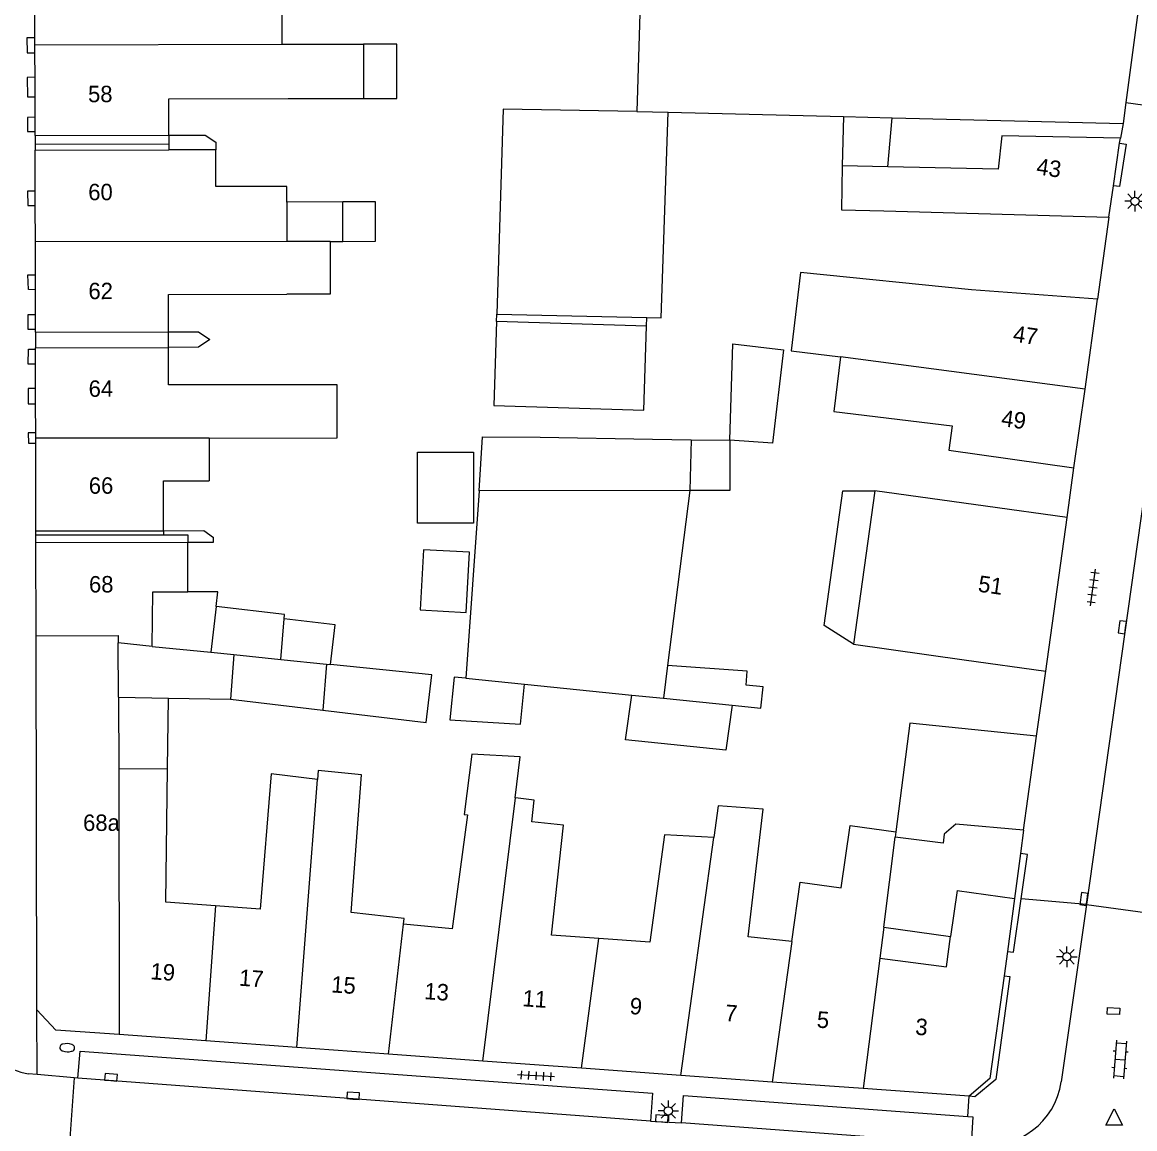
# Model space of a CAD drawing. Extents: x 132998 to 136004, y 396998 to 398512.
# Drawn here: x 133258 to 133325.6, y 397328.9 to 397396.2 of the extents above; entities that cross this region are included whole.
import ezdxf

# ---------------------------------------------------------------- set-up
doc = ezdxf.new("R2010")
doc.units = 0
for name, color, linetype in [('gg-afsc-erfafscheiding', 7, 'Continuous'), ('gg-afsc-muur', 7, 'Continuous'), ('gg-anno-huisnummerreeks BGT', 7, 'Continuous'), ('gg-bbg-bijgebouw', 7, 'Continuous'), ('gg-bbg-gedigitaliseerde bebouwing', 7, 'Continuous'), ('gg-bbg-gedigitaliseerde bebouwing onder overbouw', 7, 'Continuous'), ('gg-bbg-gedigitaliseerde bijgebouw', 7, 'Continuous'), ('gg-bbg-gedigitaliseerde overbouw', 7, 'Continuous'), ('gg-bbg-hoofdgebouw', 7, 'Continuous'), ('gg-bbg-luifel en loopbrug', 7, 'Continuous'), ('gg-bbg-pand overbouw', 7, 'Continuous'), ('gg-bbg-tussenscheiding', 7, 'Continuous'), ('gg-bbg-tussenscheiding niveau 01', 7, 'Continuous'), ('gg-knt-verharding', 7, 'Continuous'), ('gg-knt-verharding nz', 7, 'Continuous'), ('gt-grn-weggrens', 7, 'Continuous'), ('gt-symb-brandkraan', 7, 'Continuous'), ('gt-symb-klinker verharding', 7, 'Continuous'), ('gt-symb-kolk', 7, 'Continuous'), ('gt-symb-kolk center center', 7, 'Continuous'), ('gt-symb-lichtmast', 7, 'Continuous'), ('gt-symb-tegel verharding', 7, 'Continuous'), ('gt-symb-waterafsluiter', 7, 'Continuous')]:
    doc.layers.add(name, color=color, linetype=linetype)

# ---------------------------------------------------------------- blocks, each defined once
blk = doc.blocks.new('gt0-LMAST')
at = {"layer": 'gt-symb-lichtmast'}
for p, q in [((-0.182, 0.173), (-0.447, 0.438)), ((-0.005, 0.246), (-0.005, 0.621)), ((0.172, 0.173), (0.437, 0.438)), ((-0.255, -0.004), (-0.63, -0.004)), ((-0.182, -0.181), (-0.447, -0.446)), ((-0.005, -0.254), (-0.005, -0.629)), ((0.437, -0.446), (0.172, -0.181)), ((0.245, -0.004), (0.62, -0.004))]:
    blk.add_line(p, q, dxfattribs=at)
blk.add_circle((-0.005, -0.004), 0.25, dxfattribs=at)
blk = doc.blocks.new('gt0-TEG1')
at = {"layer": 'gt-symb-tegel verharding'}
for p, q in [((-1.125, 0), (1.125, 0)), ((-0.9, -0.25), (-0.9, 0.25)), ((-0.45, -0.25), (-0.45, 0.25)), ((0, -0.25), (0, 0.25)), ((0.45, -0.25), (0.45, 0.25)), ((0.9, -0.25), (0.9, 0.25))]:
    blk.add_line(p, q, dxfattribs=at)
blk = doc.blocks.new('gt0-KOLK')
at = {"layer": 'gt-symb-kolk'}
blk.add_lwpolyline([(0, 0), (0.375, 0), (0.375, 0.4), (-0.375, 0.4), (-0.375, 0), (0, 0)], dxfattribs=at)
blk = doc.blocks.new('gt0-BR')
at = {"layer": 'gt-symb-brandkraan'}
for centre, radius, start, end in [((-0.244, 0), 0.206, 107.56694, 252.43307), ((0.599, -2.664), 3, 106.89205, 107.56694), ((0, -0.691), 0.938, 73.10799, 106.89205), ((-0.599, -2.664), 3, 72.43309, 73.10799), ((0.244, 0), 0.206, 287.56695, 72.43309), ((0.599, 2.664), 3, 252.43307, 253.10797), ((0, 0.691), 0.938, 253.10797, 286.89206), ((-0.599, 2.664), 3, 286.89206, 287.56695)]:
    blk.add_arc(centre, radius, start, end, dxfattribs=at)
blk = doc.blocks.new('gt0-KOLKCC')
at = {"layer": 'gt-symb-kolk center center'}
blk.add_lwpolyline([(-0.375, 0.2), (0.375, 0.2), (0.375, -0.2), (-0.375, -0.2)], close=True, dxfattribs=at)
blk = doc.blocks.new('gt0-WAFSL')
at = {"layer": 'gt-symb-waterafsluiter'}
for p, q in [((-0.5, -0.333), (0, 0.667)), ((0, 0.667), (0.5, -0.333)), ((0.5, -0.333), (-0.5, -0.333))]:
    blk.add_line(p, q, dxfattribs=at)
blk = doc.blocks.new('gt0-KL1')
at = {"layer": 'gt-symb-klinker verharding'}
for p, q in [((-1.15, 0.3), (1.15, 0.3)), ((-1, -0.3), (-1, 0.3)), ((-0.5, 0.3), (-0.5, 0.45)), ((0, -0.3), (0, 0.3)), ((0.5, 0.3), (0.5, 0.45)), ((1, -0.3), (1, 0.3)), ((-1.15, -0.3), (1.15, -0.3)), ((-0.5, -0.45), (-0.5, -0.3)), ((0.5, -0.45), (0.5, -0.3))]:
    blk.add_line(p, q, dxfattribs=at)

msp = doc.modelspace()

# ---------------------------------------------------------------- linework, layer by layer
at = {"layer": 'gg-afsc-erfafscheiding'}
for p, q in [((133269.757, 397388.874), (133269.758, 397388.417)), ((133324.06, 397384.31), (133323.38, 397379.33))]:
    msp.add_line(p, q, dxfattribs=at)
for points in [[(133266.908, 397389.3), (133269.124, 397389.304), (133269.757, 397388.874)], [(133266.879, 397377.34), (133268.7, 397377.345), (133269.391, 397376.871), (133268.703, 397376.394), (133266.881, 397376.389)], [(133266.589, 397365.236), (133269.038, 397365.241), (133269.623, 397364.817)], [(133268.062, 397364.54), (133269.623, 397364.543), (133269.623, 397364.817)]]:
    msp.add_lwpolyline(points, dxfattribs=at)
at = {"layer": 'gg-afsc-muur'}
for p, q in [((133318.87, 397347.03), (133318.684, 397345.596)), ((133318.684, 397345.596), (133318.33, 397342.87))]:
    msp.add_line(p, q, dxfattribs=at)
at = {"layer": 'gg-bbg-bijgebouw'}
msp.add_line((133318.87, 397347.03), (133319.67, 397352.74), dxfattribs=at)
at = {"layer": 'gg-bbg-gedigitaliseerde bebouwing'}
for p, q in [((133273.767, 397394.828), (133278.739, 397394.836)), ((133278.739, 397394.836), (133278.739, 397391.524)), ((133297.259, 397390.7), (133307.92, 397390.438)), ((133307.92, 397390.438), (133310.89, 397390.365)), ((133310.89, 397390.365), (133324.93, 397390.02)), ((133269.758, 397388.417), (133266.909, 397388.412)), ((133310.626, 397387.378), (133307.855, 397387.439)), ((133310.389, 397384.693), (133324.06, 397384.31)), ((133269.366, 397370.876), (133269.366, 397368.265)), ((133309.831, 397367.666), (133308.533, 397358.326)), ((133316.567, 397366.73), (133309.831, 397367.666)), ((133321.519, 397366.042), (133316.567, 397366.73)), ((133268.061, 397361.514), (133268.062, 397364.54)), ((133308.533, 397358.326), (133315.268, 397357.39)), ((133315.268, 397357.39), (133320.221, 397356.702)), ((133263.844, 397355.107), (133263.867, 397350.761)), ((133263.867, 397350.761), (133266.827, 397350.777)), ((133287.99, 397348.993), (133287.958, 397348.997)), ((133310.372, 397341.115), (133311.076, 397346.601)), ((133314.83, 397343.34), (133314.427, 397340.547)), ((133310.372, 397341.115), (133310.131, 397339.234)), ((133314.192, 397338.714), (133314.427, 397340.547)), ((133310.131, 397339.234), (133314.192, 397338.714))]:
    msp.add_line(p, q, dxfattribs=at)
for points in [[(133308.744, 397403.349), (133308.636, 397399.48), (133305.637, 397399.564), (133305.568, 397397.065), (133295.572, 397397.343), (133295.368, 397390.732)], [(133271.437, 397401.367), (133273.755, 397401.328), (133273.767, 397394.828)], [(133266.908, 397389.3), (133266.905, 397391.514), (133274.167, 397391.524), (133278.739, 397391.524)], [(133324.76, 397389.11), (133317.563, 397389.268), (133317.339, 397387.231), (133310.626, 397387.378)], [(133274.08, 397385.234), (133274.079, 397386.183), (133269.761, 397386.178), (133269.758, 397388.417)], [(133307.855, 397387.439), (133307.797, 397384.75), (133310.389, 397384.693)], [(133276.712, 397382.839), (133276.712, 397379.621), (133274.088, 397379.621)], [(133323.38, 397379.33), (133315.712, 397379.898), (133305.316, 397380.948), (133304.744, 397376.185), (133307.736, 397375.825)], [(133266.879, 397377.34), (133266.876, 397379.611), (133274.088, 397379.621)], [(133277.15, 397374.114), (133266.884, 397374.103), (133266.881, 397376.389)], [(133307.736, 397375.825), (133307.336, 397372.49), (133314.542, 397371.624)], [(133269.366, 397370.876), (133277.15, 397370.888), (133277.15, 397374.114)], [(133314.542, 397371.624), (133314.334, 397370.13), (133321.94, 397369.07)], [(133266.589, 397365.236), (133266.587, 397368.264), (133269.366, 397368.265)], [(133265.9, 397358.201), (133265.939, 397361.514), (133268.061, 397361.514)], [(133287.958, 397348.997), (133288.266, 397351.478), (133285.321, 397351.651), (133284.866, 397347.98), (133285.064, 397347.955)], [(133269.744, 397342.424), (133266.723, 397342.647), (133266.827, 397350.777)], [(133275.946, 397350.093), (133273.135, 397350.442), (133272.46, 397342.223), (133269.744, 397342.424)], [(133281.166, 397341.304), (133281.206, 397341.655), (133278, 397342.009), (133278.629, 397350.382), (133275.99, 397350.656), (133275.946, 397350.093)], [(133293.056, 397340.426), (133290.169, 397340.634), (133290.896, 397347.325), (133288.969, 397347.534), (133289.114, 397348.852), (133287.99, 397348.993)], [(133304.777, 397340.247), (133302.126, 397340.536), (133303.04, 397348.29), (133300.311, 397348.493), (133300.044, 397346.566)], [(133285.064, 397347.955), (133284.126, 397341.015), (133281.166, 397341.304)], [(133304.777, 397340.247), (133305.283, 397343.862), (133307.791, 397343.51), (133308.324, 397347.305), (133311.116, 397346.914)], [(133300.044, 397346.566), (133297.035, 397346.737), (133296.16, 397340.203), (133293.056, 397340.426)]]:
    msp.add_lwpolyline(points, dxfattribs=at)
at = {"layer": 'gg-bbg-gedigitaliseerde bebouwing onder overbouw'}
for p, q in [((133258.778, 397389.286), (133266.908, 397389.3)), ((133258.78, 397388.398), (133266.909, 397388.412)), ((133258.801, 397377.316), (133266.879, 397377.34)), ((133258.803, 397376.365), (133266.881, 397376.389)), ((133258.825, 397365.221), (133266.589, 397365.236)), ((133258.826, 397364.522), (133268.062, 397364.54))]:
    msp.add_line(p, q, dxfattribs=at)
at = {"layer": 'gg-bbg-gedigitaliseerde bijgebouw'}
for p, q in [((133277.479, 397385.24), (133274.08, 397385.234)), ((133277.484, 397382.84), (133277.479, 397385.24)), ((133276.712, 397382.839), (133277.484, 397382.84)), ((133286.843, 397378.409), (133295.964, 397378.212)), ((133295.952, 397377.672), (133286.829, 397377.962)), ((133289.481, 397370.92), (133296.305, 397370.814)), ((133296.305, 397370.814), (133298.662, 397370.776)), ((133298.662, 397370.776), (133298.591, 397367.688)), ((133285.774, 397367.668), (133284.955, 397356.266)), ((133298.591, 397367.688), (133297.23, 397357.028)), ((133269.786, 397360.632), (133269.45, 397357.841)), ((133273.718, 397357.407), (133273.917, 397359.884)), ((133265.9, 397358.201), (133269.45, 397357.841)), ((133273.718, 397357.407), (133276.493, 397357.125)), ((133276.493, 397357.125), (133276.731, 397357.101)), ((133297.23, 397357.028), (133296.977, 397355.045)), ((133284.955, 397356.266), (133288.528, 397355.903)), ((133288.528, 397355.903), (133295.05, 397355.241)), ((133263.844, 397355.107), (133266.882, 397355.057)), ((133266.882, 397355.057), (133270.656, 397354.994)), ((133296.977, 397355.045), (133301.162, 397354.62)), ((133270.656, 397354.994), (133276.275, 397354.319))]:
    msp.add_line(p, q, dxfattribs=at)
for points in [[(133295.368, 397390.732), (133287.24, 397390.888), (133286.843, 397378.409)], [(133295.964, 397378.212), (133296.849, 397378.193), (133297.259, 397390.7)], [(133286.829, 397377.962), (133286.666, 397372.855), (133295.79, 397372.564), (133295.952, 397377.672)], [(133301.011, 397370.739), (133301.191, 397376.612), (133304.289, 397376.24), (133303.605, 397370.556), (133301.011, 397370.739)], [(133285.774, 397367.668), (133285.977, 397370.94), (133289.481, 397370.92)], [(133285.431, 397370.01), (133285.431, 397365.69), (133282.027, 397365.69), (133282.027, 397370.01), (133285.431, 397370.01)], [(133285.178, 397363.923), (133282.382, 397364.07), (133282.19, 397360.417), (133284.986, 397360.27), (133285.178, 397363.923)], [(133273.917, 397359.884), (133273.937, 397360.133), (133269.786, 397360.632)], [(133276.275, 397354.319), (133282.56, 397353.565), (133282.891, 397356.476), (133276.731, 397357.101)], [(133301.162, 397354.62), (133300.782, 397351.886), (133294.682, 397352.506), (133295.05, 397355.241)], [(133319.67, 397352.74), (133311.964, 397353.523), (133311.116, 397346.914)], [(133318.87, 397347.03), (133314.754, 397347.392), (133314.051, 397346.786), (133313.979, 397346.229), (133311.076, 397346.601)]]:
    msp.add_lwpolyline(points, dxfattribs=at)
at = {"layer": 'gg-bbg-gedigitaliseerde overbouw'}
for p, q in [((133266.908, 397389.3), (133266.909, 397388.77)), ((133266.909, 397388.77), (133266.909, 397388.412)), ((133266.881, 397376.389), (133266.879, 397377.34)), ((133266.589, 397365.236), (133266.589, 397364.985))]:
    msp.add_line(p, q, dxfattribs=at)
msp.add_lwpolyline([(133266.589, 397364.985), (133268.062, 397364.985), (133268.062, 397364.54)], dxfattribs=at)
at = {"layer": 'gg-bbg-hoofdgebouw'}
for p, q in [((133326.646, 397402.903), (133325.098, 397391.279)), ((133258.766, 397395.221), (133258.755, 397401.29)), ((133258.767, 397394.806), (133258.766, 397395.221)), ((133258.768, 397394.31), (133258.767, 397394.806)), ((133258.771, 397392.819), (133258.768, 397394.31)), ((133258.773, 397391.625), (133258.771, 397392.819)), ((133258.776, 397390.386), (133258.773, 397391.625)), ((133325.098, 397391.279), (133324.93, 397390.02)), ((133258.777, 397389.517), (133258.776, 397390.386)), ((133258.778, 397389.286), (133258.777, 397389.517)), ((133324.718, 397388.82), (133324.76, 397389.11)), ((133258.784, 397385.9), (133258.78, 397388.398)), ((133324.339, 397386.223), (133324.718, 397388.82)), ((133324.06, 397384.31), (133324.339, 397386.223)), ((133258.786, 397385.013), (133258.784, 397385.9)), ((133258.79, 397382.805), (133258.786, 397385.013)), ((133258.794, 397380.796), (133258.79, 397382.805)), ((133258.796, 397379.888), (133258.794, 397380.796)), ((133258.799, 397378.394), (133258.796, 397379.888)), ((133322.611, 397373.853), (133323.38, 397379.33)), ((133258.801, 397377.487), (133258.799, 397378.394)), ((133258.801, 397377.316), (133258.801, 397377.487)), ((133258.803, 397376.286), (133258.803, 397376.365)), ((133258.805, 397375.372), (133258.803, 397376.286)), ((133258.808, 397373.882), (133258.805, 397375.372)), ((133258.809, 397372.961), (133258.808, 397373.882)), ((133321.94, 397369.07), (133322.611, 397373.853)), ((133258.812, 397371.201), (133258.809, 397372.961)), ((133258.813, 397370.86), (133258.812, 397371.201)), ((133258.814, 397370.571), (133258.813, 397370.86)), ((133258.825, 397365.221), (133258.814, 397370.571)), ((133320.221, 397356.702), (133321.519, 397366.042)), ((133258.836, 397358.849), (133258.826, 397364.522)), ((133258.88, 397336.09), (133258.836, 397358.849)), ((133314.83, 397343.34), (133318.33, 397342.87)), ((133318.33, 397342.87), (133317.889, 397339.648)), ((133317.889, 397339.648), (133317.686, 397338.161)), ((133269.147, 397334.199), (133263.895, 397334.58)), ((133274.68, 397333.798), (133269.147, 397334.199)), ((133280.267, 397333.392), (133274.68, 397333.798)), ((133286.001, 397332.976), (133280.267, 397333.392)), ((133291.994, 397332.541), (133286.001, 397332.976)), ((133298.035, 397332.103), (133291.994, 397332.541)), ((133303.591, 397331.699), (133298.035, 397332.103)), ((133309.114, 397331.299), (133303.591, 397331.699)), ((133315.57, 397330.83), (133309.114, 397331.299))]:
    msp.add_line(p, q, dxfattribs=at)
for points in [[(133317.686, 397338.161), (133316.83, 397331.91), (133315.57, 397330.83)], [(133263.895, 397334.58), (133260.04, 397334.86), (133258.88, 397336.09)]]:
    msp.add_lwpolyline(points, dxfattribs=at)
at = {"layer": 'gg-bbg-luifel en loopbrug'}
for p, q in [((133307.92, 397390.438), (133307.855, 397387.439)), ((133310.626, 397387.378), (133310.89, 397390.365)), ((133286.829, 397377.962), (133286.843, 397378.409)), ((133295.952, 397377.672), (133295.964, 397378.212)), ((133298.662, 397370.776), (133301.011, 397370.739)), ((133266.827, 397350.777), (133266.882, 397355.057)), ((133310.372, 397341.115), (133314.427, 397340.547))]:
    msp.add_line(p, q, dxfattribs=at)
for points in [[(133278.739, 397391.524), (133280.777, 397391.524), (133280.777, 397394.839), (133278.739, 397394.836)], [(133277.484, 397382.84), (133279.477, 397382.844), (133279.473, 397385.244), (133277.479, 397385.24)], [(133301.011, 397370.739), (133301.016, 397367.692), (133298.591, 397367.688)], [(133308.533, 397358.326), (133306.754, 397359.474), (133307.894, 397367.673), (133309.831, 397367.666)], [(133269.786, 397360.632), (133269.892, 397361.514), (133268.061, 397361.514)], [(133276.731, 397357.101), (133277.021, 397359.51), (133273.917, 397359.884)], [(133301.162, 397354.62), (133302.909, 397354.443), (133303.04, 397355.736), (133302.007, 397355.843), (133302.066, 397356.688), (133297.23, 397357.028)], [(133284.955, 397356.266), (133284.251, 397356.338), (133283.987, 397353.741), (133288.28, 397353.462), (133288.528, 397355.903)]]:
    msp.add_lwpolyline(points, dxfattribs=at)
at = {"layer": 'gg-bbg-pand overbouw'}
for p, q in [((133258.778, 397389.286), (133258.779, 397388.754)), ((133258.779, 397388.754), (133258.78, 397388.398)), ((133258.801, 397377.316), (133258.803, 397376.365)), ((133258.825, 397364.987), (133258.825, 397365.221)), ((133258.826, 397364.522), (133258.825, 397364.987))]:
    msp.add_line(p, q, dxfattribs=at)
at = {"layer": 'gg-bbg-tussenscheiding'}
for p, q in [((133258.767, 397394.806), (133273.767, 397394.828)), ((133295.368, 397390.732), (133297.259, 397390.7)), ((133274.08, 397385.234), (133274.085, 397382.834)), ((133274.085, 397382.834), (133258.79, 397382.805)), ((133276.712, 397382.839), (133274.085, 397382.834)), ((133322.611, 397373.853), (133307.736, 397375.825)), ((133269.366, 397370.876), (133258.813, 397370.86)), ((133298.591, 397367.688), (133285.774, 397367.668)), ((133263.844, 397355.107), (133263.826, 397358.412)), ((133265.9, 397358.201), (133263.826, 397358.412)), ((133269.45, 397357.841), (133270.852, 397357.698)), ((133270.852, 397357.698), (133270.656, 397354.994)), ((133270.852, 397357.698), (133273.718, 397357.407)), ((133276.493, 397357.125), (133276.275, 397354.319)), ((133295.05, 397355.241), (133296.977, 397355.045)), ((133263.867, 397350.761), (133263.895, 397334.58)), ((133274.68, 397333.798), (133275.946, 397350.093)), ((133286.001, 397332.976), (133287.99, 397348.993)), ((133298.035, 397332.103), (133300.044, 397346.566)), ((133311.116, 397346.914), (133311.076, 397346.601)), ((133269.744, 397342.424), (133269.147, 397334.199)), ((133280.267, 397333.392), (133281.166, 397341.304)), ((133291.994, 397332.541), (133293.056, 397340.426)), ((133304.777, 397340.247), (133303.591, 397331.699)), ((133310.131, 397339.234), (133309.114, 397331.299))]:
    msp.add_line(p, q, dxfattribs=at)
msp.add_lwpolyline([(133258.836, 397358.849), (133263.825, 397358.858), (133263.826, 397358.412)], dxfattribs=at)
at = {"layer": 'gg-bbg-tussenscheiding niveau 01'}
for p, q in [((133258.779, 397388.754), (133266.909, 397388.77)), ((133258.825, 397364.987), (133266.589, 397364.985))]:
    msp.add_line(p, q, dxfattribs=at)
at = {"layer": 'gg-knt-verharding'}
for p, q in [((133324.93, 397390.02), (133324.76, 397389.11)), ((133327.62, 397377.531), (133322.696, 397342.49)), ((133321.519, 397366.042), (133321.94, 397369.07)), ((133319.67, 397352.74), (133320.221, 397356.702)), ((133322.696, 397342.49), (133321.167, 397331.701)), ((133322.696, 397342.49), (133328.63, 397341.694)), ((133258.909, 397332.148), (133258.358, 397332.194)), ((133261.157, 397331.958), (133258.909, 397332.148)), ((133261.157, 397331.958), (133260.864, 397327.975)), ((133261.378, 397331.939), (133261.157, 397331.958)), ((133296.188, 397329.324), (133298.069, 397329.206))]:
    msp.add_line(p, q, dxfattribs=at)
for points in [[(133258.766, 397395.221), (133258.278, 397395.22), (133258.293, 397394.309), (133258.768, 397394.31)], [(133258.771, 397392.819), (133258.302, 397392.818), (133258.318, 397391.624), (133258.773, 397391.625)], [(133258.776, 397390.386), (133258.306, 397390.385), (133258.305, 397389.516), (133258.777, 397389.517)], [(133324.718, 397388.82), (133325.112, 397388.763), (133324.71, 397386.169), (133324.339, 397386.223)], [(133258.784, 397385.9), (133258.314, 397385.899), (133258.338, 397385.012), (133258.786, 397385.013)], [(133258.796, 397379.888), (133258.373, 397379.904), (133258.337, 397380.812), (133258.794, 397380.796)], [(133258.801, 397377.487), (133258.358, 397377.485), (133258.358, 397378.392), (133258.799, 397378.394)], [(133258.805, 397375.372), (133258.353, 397375.371), (133258.367, 397376.285), (133258.803, 397376.286)], [(133258.808, 397373.882), (133258.347, 397373.881), (133258.352, 397372.96), (133258.809, 397372.961)], [(133258.812, 397371.201), (133258.354, 397371.2), (133258.369, 397370.57), (133258.814, 397370.571)], [(133318.73, 397342.835), (133319.113, 397345.54), (133318.684, 397345.596)], [(133317.889, 397339.648), (133318.272, 397339.595), (133318.73, 397342.835)], [(133317.686, 397338.161), (133318.046, 397338.112), (133317.197, 397331.858), (133315.915, 397330.805), (133315.57, 397330.83)], [(133261.378, 397331.939), (133261.515, 397333.586), (133296.308, 397331.012), (133296.188, 397329.324)], [(133298.069, 397329.206), (133298.203, 397330.883), (133315.478, 397329.599)], [(133315.478, 397329.599), (133315.784, 397329.576), (133315.69, 397327.889)]]:
    msp.add_lwpolyline(points, dxfattribs=at)
for centre, radius, start, end in [((133259.441, 397337.562), 5.476, 181.82058, 258.58881), ((133316.675, 397332.379), 4.543, 263.1331, 351.41443)]:
    msp.add_arc(centre, radius, start, end, dxfattribs=at)
at = {"layer": 'gg-knt-verharding nz'}
for p, q in [((133296.188, 397329.324), (133261.378, 397331.939)), ((133315.69, 397327.889), (133298.069, 397329.206))]:
    msp.add_line(p, q, dxfattribs=at)
at = {"layer": 'gt-grn-weggrens'}
for p, q in [((133325.098, 397391.279), (133327.364, 397390.965)), ((133322.696, 397342.49), (133318.73, 397342.835)), ((133258.909, 397332.148), (133258.88, 397336.09)), ((133315.478, 397329.599), (133315.57, 397330.83))]:
    msp.add_line(p, q, dxfattribs=at)

# ---------------------------------------------------------------- block references
at = {"layer": 'gt-symb-brandkraan', "rotation": -2.5791475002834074}
msp.add_blockref('gt0-BR', (133260.726, 397333.786), dxfattribs=at)
at = {"layer": 'gt-symb-klinker verharding', "rotation": -94.64472160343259}
msp.add_blockref('gt0-KL1', (133324.74, 397333.065), dxfattribs=at)
at = {"layer": 'gt-symb-kolk'}
for p, rotation in [((133325.082, 397359.338), 82.12907949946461), ((133322.737, 397342.806), 81.95093829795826), ((133263.378, 397331.783), -4.359151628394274), ((133278.095, 397330.661), -4.2448620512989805), ((133296.866, 397329.268), -4.701808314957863)]:
    msp.add_blockref('gt0-KOLK', p, dxfattribs=dict(at, rotation=rotation))
at = {"layer": 'gt-symb-kolk center center', "rotation": 177.30638896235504}
msp.add_blockref('gt0-KOLKCC', (133324.352, 397336.018), dxfattribs=at)
at = {"layer": 'gt-symb-lichtmast'}
for p in [(133325.655, 397385.284), (133321.51, 397339.324), (133297.283, 397329.946)]:
    msp.add_blockref('gt0-LMAST', p, dxfattribs=at)
at = {"layer": 'gt-symb-tegel verharding'}
for p, rotation in [((133323.098, 397361.775), 82.53402593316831), ((133289.228, 397332.076), 176.44511132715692)]:
    msp.add_blockref('gt0-TEG1', p, dxfattribs=dict(at, rotation=rotation))
at = {"layer": 'gt-symb-waterafsluiter'}
msp.add_blockref('gt0-WAFSL', (133324.381, 397329.406), dxfattribs=at)

# ---------------------------------------------------------------- texts
at = {"layer": 'gg-anno-huisnummerreeks BGT'}
for s, rotation, p in [('58', 0.1, (133261.997, 397391.305)), ('43', 351.7, (133319.614, 397386.923)), ('60', 0.1, (133262.008, 397385.341)), ('62', 0.1, (133262.02, 397379.322)), ('47', 352, (133318.192, 397376.74)), ('64', 0.1, (133262.031, 397373.381)), ('49', 352, (133317.473, 397371.612)), ('66', 0.1, (133262.043, 397367.485)), ('68', 0.1, (133262.054, 397361.479)), ('51', 352.1, (133316.069, 397361.535)), ('68a', 0.1, (133261.694, 397346.971)), ('19', 355.9, (133265.764, 397337.953)), ('17', 355.9, (133271.151, 397337.562)), ('15', 355.9, (133276.753, 397337.156)), ('13', 355.9, (133282.413, 397336.745)), ('11', 355.9, (133288.382, 397336.312)), ('9', 355.9, (133294.903, 397335.839)), ('7', 355.8, (133300.698, 397335.418)), ('5', 355.9, (133306.277, 397335.013)), ('3', 355.9, (133312.268, 397334.579))]:
    msp.add_text(s, height=1, rotation=rotation, dxfattribs=at).set_placement(p)

doc.saveas('drawing.dxf')
